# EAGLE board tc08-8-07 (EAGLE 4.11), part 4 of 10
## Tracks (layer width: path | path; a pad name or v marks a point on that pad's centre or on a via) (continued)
ENI  (via drill 0.61) (continued)
  Top 0.254: v55.92,263.19 54.33,261.61 54.33,259.7 54.65,259.38 54.65,258.75 54.33,258.43 54.33,249.23 55.28,248.27 A25.L1 | v57.82,265.1 66.39,273.67 66.39,280.02 77.51,291.13 v77.51,294.94 | v95.92,295.9 103.22,295.9 103.22,295.26 120.05,278.43 127.04,278.43 v127.04,276.85 | v136.56,275.9 v136.56,271.77 | v283.88,117.14 283.88,114.92 C07.L1 | v281.98,65.08 282.29,64.76 v282.29,50.15 | v273.4,50.15 273.4,40.31 v274.04,39.68 | v272.45,36.5 270.23,34.28 270.23,29.2 v270.55,28.88 | v260.7,26.66 259.43,26.66 v257.85,28.25 | v174.66,30.78 171.49,30.78 171.49,18.72 170.53,17.77 165.14,17.77 v165.14,19.35 | v160.69,18.72 158.47,20.94 155.29,20.94 v155.29,19.35 | v147.99,19.35 145.77,19.35 145.77,19.67 145.13,20.31 133.07,20.31 133.07,18.4 127.99,13.32 126.4,13.32 v126.4,13.96 | v17.82,58.72 15.59,60.95 15.59,74.28 12.1,77.77 12.1,87.94 12.42,88.25 12.42,199.38 v12.1,199.7
  Route2 0.254: v277.53,117.14 276.26,117.14 270.55,111.43 270.55,109.84 266.42,105.72 266.42,98.41 271.82,93.02 271.5,92.7 271.5,90.79 273.09,89.21 273.4,89.21 274.99,87.62 274.99,87.3 284.2,78.09 284.2,75.24 282.93,73.97 282.93,66.03 v281.98,65.08 | v165.14,19.35 163.23,21.26 v160.69,18.72 | v155.29,19.35 153.71,20.94 149.58,20.94 v147.99,19.35 | v12.1,199.7 20.04,207.63 20.99,207.63 25.12,211.76 25.12,212.71 36.23,223.83 36.23,224.14 40.36,228.27 40.36,230.49 53.69,243.83 53.69,245.42 55.28,247 A25.L1
  Route15 0.254: v167.68,272.4 167.99,272.4 174.34,266.05 174.34,265.1 v177.84,261.61 | v209.27,261.61 215.94,261.61 218.48,259.07 221.65,259.07 223.24,257.48 A12.H1 | v202.92,27.61 197.52,33.01 188.31,33.01 185.46,30.15 184.5,31.1 v184.19,31.1
  Bottom 0.254: v55.92,263.19 v57.82,265.1 | v77.51,294.94 77.82,294.63 81,294.63 82.27,295.9 v95.92,295.9 | v127.04,276.85 127.04,274.94 135.61,274.94 v136.56,275.9 | v136.56,271.77 136.88,271.45 144.18,271.45 144.5,271.77 165.77,271.77 166.41,272.4 v167.68,272.4 | v177.84,261.61 v209.27,261.61 | v283.88,117.14 282.29,118.73 279.12,118.73 v277.53,117.14 | v282.29,50.15 281.66,49.52 275.31,49.52 274.67,50.15 v273.4,50.15 | v274.04,39.68 272.77,38.4 272.77,36.5 v272.45,36.5 | v270.55,28.88 268.32,26.66 v260.7,26.66 | v257.85,28.25 256.89,27.29 238.16,27.29 237.53,26.66 234.03,26.66 233.4,27.29 208.95,27.29 208.63,27.61 205.78,27.61 205.46,27.29 203.24,27.29 v202.92,27.61 | v184.19,31.1 183.55,30.47 174.98,30.47 v174.66,30.78 | v126.4,13.96 125.77,14.59 109.89,14.59 108.94,15.54 61,15.54 v17.82,58.72
ENI\  (via drill 0.61)
  Top 0.254: v306.42,120.64 309.92,124.13 v309.92,124.77 | v324.52,139.37 324.2,139.69 324.2,145.08 326.43,147.31 326.43,152.71 v325.79,153.34 | v321.35,160.96 321.03,161.28 321.03,165.72 321.35,166.04 321.35,170.49 321.03,170.8 v321.03,173.66 | v328.33,175.56 328.33,177.15 B03.L2 | v287.37,107.3 C07.M1
  Route2 0.254: v296.26,110.16 296.26,110.48 v306.42,120.64 | v309.92,124.77 v322.3,137.15
  Route15 0.254: v325.79,153.34 320.71,158.42 320.71,160.33 v321.35,160.96
  Bottom 0.254: v287.37,107.3 288.01,106.67 291.5,106.67 293.41,108.57 294.68,108.57 v296.26,110.16 | v322.3,137.15 v324.52,139.37 | v321.03,173.66 323.25,175.88 328.01,175.88 v328.33,175.56
FR_00  (via drill 0.61)
  Top 0.254: 218.79,163.18 218.79,185.09 219.11,185.41 219.11,188.27 217.84,189.54 217.84,193.03 B12.E2 | 218.79,163.18 218.79,161.28 218.48,160.96 218.48,158.1 219.11,157.47 219.11,136.2 218.79,135.88 218.79,96.19 218.48,95.87 218.48,93.33 217.84,92.7 C12.U2 | v69.89,261.29 73.38,261.29 73.38,269.23 80.68,276.53 v82.59,276.53 | v89.89,278.12 97.51,285.74 97.51,292.41 98.78,293.68 101.64,293.68 101.64,268.91 v101.95,268.59 | v105.13,268.28 107.67,268.28 v107.67,264.47 | v130.21,263.19 130.53,262.88 v130.53,257.48 | v151.8,256.21 152.12,255.89 152.12,250.81 149.58,248.27 149.58,240.33 v151.48,238.43 | v262.29,152.39 261.97,152.07 v261.97,148.26 | 218.79,163.18 v219.43,163.18
  Route2 0.254: v82.59,276.53 83.54,277.48 86.71,277.48 88.3,279.07 88.94,279.07 v89.89,278.12 | v283.56,161.28 283.56,160.01 282.61,159.05 282.61,154.93 v280.39,152.71
  Route15 0.254: v156.88,237.8 156.88,237.48 159.42,234.94 160.37,234.94 170.22,225.09 171.17,225.09 180.06,216.21 181.01,216.21 v184.19,213.03 | v192.76,212.71 194.66,212.71 201.33,206.05 202.92,206.05 207.05,201.92 207.36,201.92 213.71,195.57 215.3,195.57 216.89,193.98 B12.E2 | v246.42,148.26 242.92,148.26 241.34,149.85 239.75,149.85 v227.37,162.23
  Bottom 0.254: v69.89,261.29 69.57,261.61 57.19,261.61 56.23,260.66 A25.F1 | v101.95,268.59 102.27,268.28 v105.13,268.28 | v107.67,264.47 107.99,264.78 125.45,264.78 127.99,262.24 129.26,262.24 v130.21,263.19 | v130.53,257.48 132.12,255.89 151.48,255.89 v151.8,256.21 | v151.48,238.43 153.07,236.84 155.29,236.84 156.25,237.8 v156.88,237.8 | v184.19,213.03 185.46,211.76 191.81,211.76 v192.76,212.71 | v283.56,161.28 284.83,162.55 286.42,162.55 286.74,162.23 B07.S1 | v280.39,152.71 278.8,151.12 269.91,151.12 269.59,151.43 266.1,151.43 265.78,151.12 263.56,151.12 v262.29,152.39 | v261.97,148.26 261.66,148.58 246.73,148.58 v246.42,148.26 | v227.37,162.23 226.41,163.18 v219.43,163.18
FR_00\  (via drill 0.61)
  Top 0.254: C12.P1 223.87,109.21 222.6,110.48 222.6,115.56 223.56,116.51 223.56,116.83 C12.K1 | v296.58,155.88 297.22,155.24 v297.22,153.98
  Route2 0.254: v246.42,142.55 246.1,142.23 245.46,142.23 242.92,139.69 242.61,139.69 225.14,122.22 225.14,121.59 224.19,120.64 224.19,118.1 C12.K1 | v265.78,143.18 268.64,140.32 272.77,144.45 273.4,144.45 v283.56,154.61
  Route15 0.254: v290.23,154.61 289.6,155.24 288.01,155.24 B07.U1
  Bottom 0.254: v290.23,154.61 290.55,154.29 294.36,154.29 295.95,155.88 v296.58,155.88 | v297.22,153.98 297.53,154.29 309.6,154.29 312.77,157.47 321.66,157.47 321.98,157.15 324.2,157.15 327.06,160.01 334.36,160.01 335,160.64 338.81,160.64 339.76,161.59 339.76,169.53 337.22,169.53 335.63,171.12 B03.N1 | v246.42,142.55 248,140.96 256.89,140.96 257.21,140.64 257.85,140.64 258.8,141.59 263.88,141.59 265.47,143.18 v265.78,143.18 | v283.56,154.61 284.2,155.24 286.74,155.24 B07.U1
FR_01  (via drill 0.61)
  Top 0.254: v222.6,16.5 222.6,29.51 221.02,31.1 D12.R1 | B07.V2 278.17,151.75 278.8,151.12 278.8,140.64 279.12,140.32 279.12,138.42 278.8,138.1 278.8,134.29 279.12,133.97 279.12,87.94 277.85,86.66 277.85,71.74 276.58,70.47 276.58,22.85 277.85,21.58 D07.V2 | v171.49,133.34 171.17,133.65 171.17,155.56 167.99,158.74 167.99,162.55 165.14,165.4 v165.14,173.66 | v171.17,173.66 171.17,188.58 171.8,189.22 171.8,196.84 v172.12,197.15 | v168.63,198.11 168.31,198.43 168.31,201.6 163.23,206.68 v163.23,218.11 | v157.83,218.11 155.93,220.02 155.93,255.89 v156.25,256.21 | v186.41,32.37 184.19,34.6 v184.19,38.4 | v29.88,68.25 25.75,72.38 25.75,229.22 26.07,229.54 26.07,230.81 25.75,231.13 v25.75,242.56 | v57.5,242.56 57.19,242.87 57.19,246.37 57.5,246.68 57.5,255.58 58.46,256.53 A25.H1
  Bottom 0.254: v222.6,16.5 266.74,16.5 267.37,17.13 272.45,17.13 274.36,19.04 D07.V2 | v171.49,133.34 171.8,133.34 176.25,128.89 181.01,128.89 183.23,131.11 183.23,131.75 182.92,132.07 182.92,132.7 C15.D1 | v165.14,173.66 165.45,173.34 171.17,173.34 | 171.17,173.34 184.19,173.34 185.14,174.3 B15.M1 | 156.25,258.43 244.19,258.43 245.15,257.48 248.64,257.48 A10.H1 | 156.25,258.43 77.19,258.43 76.87,258.11 74.01,258.11 73.7,258.43 60.36,258.43 59.41,257.48 A25.H1 | v171.17,173.66 171.17,173.34 | v172.12,197.15 171.17,198.11 v168.63,198.11 | v157.83,218.11 v163.23,218.11 | 156.25,258.43 v156.25,256.21 | v186.41,32.37 188.31,30.47 208.63,30.47 208.95,30.78 213.4,30.78 213.71,30.47 219.11,30.47 220.06,31.42 D12.R1 | v184.19,38.4 183.23,39.36 165.14,39.36 161.64,42.85 148.94,42.85 148.63,43.17 83.54,43.17 83.22,43.49 81.95,43.49 81.63,43.17 67.03,43.17 41.95,68.25 v29.88,68.25 | v25.75,242.56 v57.5,242.56
FR_01\  (via drill 0.61)
  Top 0.254: v305.79,150.48 305.47,150.8 305.47,154.61 305.15,154.93 305.15,171.12 v306.42,172.39 | v310.55,174.61 310.87,174.93 310.87,183.5 311.19,183.82 311.19,185.41 306.74,189.85 306.74,193.03 B05.E2 | v216.89,259.38 216.89,258.11 217.21,257.8 A12.H2 | v240.07,270.81 v241.97,272.72 | v247.69,272.72 248,273.04 248,285.1 260.07,297.17 275.94,297.17 v275.94,289.86 | v322.3,289.55 336.59,289.55 336.59,257.8 336.9,257.48 336.9,255.26 339.76,252.4 339.76,240.65 v338.81,239.7
  Route2 0.254: v240.07,270.81 v233.08,263.83 | v338.81,239.7 341.35,237.16 333.41,229.22 333.41,225.09 331.51,223.19 331.51,212.71 329.92,211.12 329.92,208.9 324.84,203.82 324.84,201.28 324.2,200.65 324.2,196.84 v322.62,195.25
  Bottom 0.254: v305.79,150.48 288.96,150.48 287.69,151.75 285.15,151.75 284.83,152.07 B07.V1 | v306.42,172.39 308.65,174.61 v310.55,174.61 | 322.62,194.93 308.96,194.93 308.01,193.98 307.06,193.98 B05.E2 | 322.62,194.93 326.43,194.93 328.01,196.52 B03.D2 | v216.89,259.38 216.89,262.24 231.49,262.24 v233.08,263.83 | v241.97,272.72 242.29,272.4 244.83,272.4 245.46,271.77 246.73,271.77 v247.69,272.72 | v275.94,289.86 276.26,289.55 v322.3,289.55 | v322.62,195.25 322.62,194.93
FR_02  (via drill 0.61)
  Top 0.254: v268.64,18.09 268.64,15.86 268.01,15.23 266.42,15.23 266.42,20.31 v265.47,21.26 | v262.29,18.72 262.29,15.23 256.58,9.51 231.49,9.51 v231.49,18.09 | v211.49,17.77 201.33,7.61 31.47,7.61 31.47,99.68 31.15,100 31.15,100.63 31.47,100.95 31.47,147.94 28.93,150.48 28.93,220.02 v29.25,220.33 | v19.09,220.97 18.77,221.29 v18.77,255.26 | v272.45,92.38 272.45,89.84 273.09,89.21 v273.09,88.25 | v293.09,58.72 292.77,58.41 292.77,54.92 292.45,54.6 292.45,53.33 294.99,50.79 294.99,48.25 295.31,47.93 v295.31,46.34 | v282.93,39.36 282.61,39.04 282.61,26.66 281.98,26.02 281.98,23.48 281.34,22.85 D07.U2
  Route2 0.254: v265.47,21.26 264.83,21.26 v262.29,18.72 | v217.52,17.13 213.4,17.13 212.13,18.4 v211.49,17.77 | v272.45,92.38 277.85,97.78 278.48,97.78 286.42,105.72 286.42,107.62 289.6,110.8 285.47,114.92 285.47,126.67 287.06,128.26 287.06,129.53 C07.E1
  Route15 0.254: v273.09,88.25 273.09,87.94 275.94,85.08 275.94,82.86 284.83,73.97 284.83,71.11 285.47,70.47 285.47,66.35 v293.09,58.72
  Bottom 0.254: v268.64,18.09 268.96,17.77 272.13,17.77 274.67,20.31 278.8,20.31 280.39,21.89 D07.U2 | v231.49,18.09 231.18,17.77 223.56,17.77 223.24,18.09 221.65,18.09 220.7,17.13 v217.52,17.13 | v29.25,220.33 28.61,220.97 v19.09,220.97 | v18.77,255.26 19.4,255.89 30.2,255.89 32.74,258.43 53.06,258.43 55.28,256.21 55.28,254.62 A25.J1 | v295.31,46.34 295.31,44.44 293.41,44.44 288.33,39.36 v282.93,39.36
FR_02\  (via drill 0.61)
  Top 0.254: v326.43,164.77 326.74,165.09 326.74,172.71 v326.43,173.02 | v329.28,185.73 v329.28,188.27 | v331.19,190.17 331.51,190.49 331.51,193.03 B03.E2 | v284.2,129.53 C07.F1
  Route2 0.254: v299.76,133.65 299.76,134.29 318.49,153.02 318.81,153.02 320.08,154.29 320.08,154.61 323.89,158.42 323.89,162.23 v326.43,164.77 | v326.43,173.02 326.43,173.66 326.74,173.98 326.74,176.83 327.06,177.15 327.06,178.42 v332.46,183.82 | v329.28,188.27 v331.19,190.17
  Bottom 0.254: v284.2,129.53 286.74,132.07 291.5,132.07 293.09,133.65 295.31,133.65 296.26,134.61 298.49,134.61 299.44,133.65 v299.76,133.65 | v332.46,183.82 330.55,185.73 v329.28,185.73
FR_03  (via drill 0.61)
  Top 0.254: v28.29,245.73 28.29,230.49 v26.71,228.9 | v16.55,201.6 16.23,201.28 16.23,156.2 v17.82,154.61 | v83.86,182.55 82.9,181.6 82.9,176.83 79.73,173.66 79.73,151.75 80.36,151.12 v80.36,148.58 79.73,147.94 79.73,55.87 v81.32,54.28 | v176.57,169.21 175.61,168.26 175.61,165.4 B15.R2 | v294.04,26.98 295.31,28.25 295.31,32.06 295.63,32.37 295.63,37.45 295.31,37.77 295.31,41.58 293.72,43.17 v293.72,45.71 | v180.69,15.54 181.01,15.86 181.01,30.47 178.15,33.32 178.15,33.96 v177.52,34.6 | v156.56,35.23 158.47,37.14 158.47,39.68 v154.34,43.8 | v144.82,41.58 143.23,43.17 143.23,46.03 v143.86,46.66 | v281.34,62.85 279.75,61.27 v279.75,56.5
  Route2 0.254: v284.52,124.13 284.52,122.86 282.93,121.27 282.93,117.46 v281.34,115.88 | v296.26,91.11 296.26,90.16 295.63,89.52 295.63,87.3 287.37,79.05 287.37,74.92 286.1,73.65 286.1,68.88 284.52,67.3 284.52,66.03 v281.34,62.85
  Route15 0.254: v26.71,228.9 v23.53,225.73 | v118.78,186.36 122.27,182.87 v122.27,182.55 | v128.31,183.18 128.62,183.18 129.26,182.55 130.21,182.55 v134.66,178.11 | v160.06,176.83 161.64,175.25 161.64,174.61 162.91,173.34 163.55,173.34 v169.26,167.63 | v274.36,31.42 262.61,19.67 260.07,19.67 259.43,20.31 253.08,20.31 249.91,23.48 248.32,23.48 v247.69,22.85 | v151.17,40.63 v154.34,43.8 | v281.34,115.88 284.52,115.88 288.64,111.75 288.64,108.25 288.96,107.94 288.96,106.67 291.18,104.44 291.18,102.86 294.99,99.05 294.99,98.1 295.63,97.46 296.58,97.46 298.49,95.55 298.49,93.02 298.8,92.7 298.8,92.06 297.22,90.47 296.58,91.11 v296.26,91.11 | v293.72,45.71 v284.52,54.92
  Bottom 0.254: v28.29,245.73 49.57,245.73 52.74,248.91 56.55,248.91 58.14,250.49 A25.K1 | v23.53,225.73 21.94,224.14 19.72,224.14 17.82,226.05 17.18,226.05 9.88,218.74 9.88,201.6 v16.55,201.6 | v17.82,154.61 21.63,150.8 21.63,149.21 78.46,149.21 79.09,148.58 v80.36,148.58 | v83.86,182.55 84.17,182.87 109.57,182.87 112.75,186.04 118.46,186.04 v118.78,186.36 | v122.27,182.55 122.59,182.87 126.72,182.87 127.04,183.18 v128.31,183.18 | v134.66,178.11 135.61,177.15 136.88,177.15 137.51,176.52 159.74,176.52 v160.06,176.83 | v169.26,167.63 169.9,166.99 176.88,166.99 177.52,167.63 177.52,169.21 v176.57,169.21 | v294.04,26.98 290.23,26.98 284.52,21.26 284.52,19.67 D07.V1 | v293.72,45.71 290.55,42.53 286.42,42.53 284.52,40.63 282.29,40.63 281.66,39.99 279.75,39.99 279.12,39.36 279.12,33.01 275.94,33.01 v274.36,31.42 | v247.69,22.85 247.05,23.48 241.34,23.48 240.38,22.53 238.8,22.53 236.57,20.31 218.79,20.31 213.71,15.23 181.01,15.23 v180.69,15.54 | v177.52,34.6 176.57,33.64 169.9,33.64 169.26,34.28 167.99,34.28 167.36,33.64 159.1,33.64 157.52,35.23 v156.56,35.23 | v151.17,40.63 150.53,39.99 146.4,39.99 v144.82,41.58 | v143.86,46.66 143.86,47.93 142.28,49.52 86.08,49.52 v81.32,54.28 | v284.52,124.13 281.66,124.13 C07.H2 | v279.75,56.5 281.02,55.23 284.2,55.23 v284.52,54.92
FR_03\  (via drill 0.61)
  Top 0.254: v312.14,122.22 311.5,122.86 311.5,139.37 v313.41,141.27 | v319.44,144.77 318.49,145.72 v318.49,153.98 | v341.35,166.68 341.67,166.99 v341.67,169.85 | v341.03,179.37 v341.03,182.23 | v277.85,123.49 C07.J2 | v313.73,164.45 314.04,164.14 314.04,158.74 v313.73,158.42
  Route2 0.254: v316.58,144.45 v313.41,141.27
  Route15 0.254: v291.18,122.86 293.09,120.96 294.99,120.96 v296.26,122.22 | v293.41,183.18 294.99,181.6 294.99,177.79 295.31,177.47 295.31,176.2 v302.3,169.21 | v315.63,156.52 v313.73,158.42
  Bottom 0.254: v277.85,123.49 278.17,123.18 279.75,123.18 280.39,122.54 290.87,122.54 v291.18,122.86 | v296.26,122.22 296.58,122.54 311.82,122.54 v312.14,122.22 | v316.58,144.45 316.9,144.77 v319.44,144.77 | v341.35,166.68 342.62,166.68 342.62,163.5 336.27,157.15 325.16,157.15 322.3,154.29 318.81,154.29 v318.49,153.98 318.17,154.29 317.85,154.29 v315.63,156.52 | v341.67,169.85 342.62,170.8 342.62,179.37 v341.03,179.37 | v341.03,182.23 333.41,182.23 332.46,181.28 B03.K2 | v293.41,183.18 293.09,182.87 269.28,182.87 268.01,184.14 B08.J2 | v302.3,169.21 302.3,166.99 309.92,166.99 312.46,164.45 v313.73,164.45
GND  (via drill 0.61)
  Top 0.635: D11.P1 236.89,34.28 236.89,30.47 238.16,29.2 238.16,27.93 235.94,25.71 234.03,25.71 D11.T1 | D04.U2 319.76,22.53 321.98,24.75 D04.T1 321.98,26.02 321.98,31.1 D04.R1 321.98,32.37 321.98,37.45 D04.N1 | D03.R2 328.33,32.37 328.33,37.45 D03.N2 328.33,38.72 328.33,43.8 D03.L2 328.33,45.07 328.33,50.15 D03.J2 D03.F2 | D02.U2 345.16,22.53 347.06,22.53 347.06,25.07 D02.T1 347.38,26.02 347.38,31.1 D02.R1 347.38,32.37 347.38,37.45 D02.N1 | D03.U2 332.46,22.53 334.68,24.75 D03.T1 D03.R1 334.68,32.37 334.68,37.45 D03.N1 | D02.N2 341.03,37.45 341.03,32.37 D02.R2 | D05.U2 307.06,22.53 309.28,24.75 D05.T1 309.28,26.02 309.28,31.1 D05.R1 309.28,32.37 309.28,37.45 D05.N1 D05.L1 | D05.S1 312.46,29.2 312.46,34.28 D05.P1 312.46,35.55 312.46,40.63 D05.M1 312.46,41.9 312.46,46.98 D05.K1 | D04.R2 D04.N2 D04.L2 D04.J2 | D02.L2 341.03,45.07 341.03,50.15 D02.J2 341.03,51.42 341.03,56.5 D02.F2 | D05.F1 309.28,56.5 309.28,51.42 D05.J1 | D05.E1 312.46,59.68 312.46,54.6 D05.H1 | D06.F2 290.23,56.5 290.23,51.42 D06.J2 290.23,50.15 290.23,45.07 D06.L2 290.23,43.8 290.23,38.72 D06.N2 290.23,37.45 290.23,32.37 D06.R2 | D07.T1 284.52,24.75 286.74,22.53 D07.U1 | D06.U2 294.36,22.53 296.58,24.75 D06.T1 296.58,26.02 296.58,31.1 D06.R1 296.58,32.37 296.58,37.45 D06.N1 | D05.R2 302.93,32.37 302.93,37.45 D05.N2 D05.L2 | D03.A1 337.86,72.38 337.86,67.3 D03.C1 | D02.A1 350.56,72.38 350.56,67.3 D02.C1 | D04.C1 D04.A1 | D06.A1 299.76,72.38 299.76,67.3 D06.C1 | D05.J2 302.93,51.42 302.93,56.5 D05.F2 302.93,57.77 302.93,62.85 D05.D2 | D05.C1 D05.A1 312.77,88.57 310.23,91.11 310.23,94.28 309.92,94.6 C05.T1
  Top 0.635: B02.T1 347.38,158.1 347.38,153.02 B02.V1 | B03.T1 334.68,158.1 334.68,153.02 B03.V1 | B04.T1 321.98,158.1 321.98,153.02 B04.V1 | C05.C2 306.74,137.15 307.38,137.78 307.38,140.64 309.6,142.86 B05.V1 309.28,153.02 309.28,158.1 B05.T1 309.92,159.37 309.92,162.23 311.19,163.5 311.19,166.36 312.46,167.63 B05.P1 312.46,168.9 312.46,171.44 310.55,173.34 307.38,173.34 307.38,175.56 307.22,175.72 | 79.89,252.56 79.41,252.08 79.41,246.37 78.14,245.1 A23.M2 | 79.89,252.56 80.68,253.35 A23.J1 | 79.89,252.56 79.73,252.72 76.24,256.21 76.24,258.43 74.97,259.7 A23.F2 74.97,260.97 75.6,261.61 75.6,265.42 77.51,267.32 77.51,269.23 A23.C2 | AB19.AS2 AB19.AU2 128.31,226.05 126.08,228.27 AB19.AT2 125.13,229.22 125.13,234.3 AB19.AR2 125.77,235.57 126.4,236.21 126.4,240.02 127.04,240.65 127.04,248.91 128.31,250.18 AB19.AK2 127.99,251.13 126.88,252.24 | 126.88,252.24 125.77,253.35 AB19.AJ2 | AB19.AC2 128.31,269.23 127.04,267.96 127.04,252.4 126.88,252.24 | A02.T1 A02.R1 347.38,235.57 347.38,240.65 A02.N1 | A04.U2 319.76,225.73 321.98,227.95 A04.T1 321.98,229.22 321.98,234.3 A04.R1 321.98,235.57 321.98,240.65 A04.N1 | A03.N2 328.33,240.65 328.33,235.57 A03.R2 | A03.T1 334.68,229.22 334.68,234.3 A03.R1 A03.N1 | A02.R2 A02.N2 341.03,241.92 341.03,247 A02.L2 341.03,248.27 341.03,253.35 A02.J2 341.03,254.62 341.03,259.7 A02.F2 | AB01.AL2 354.68,247.96 356.91,250.18 AB01.AK2 356.91,251.45 356.91,256.53 AB01.AH2 | A05.U2 307.06,225.73 309.28,227.95 A05.T1 309.28,229.22 309.28,234.3 A05.R1 | A05.S1 A05.P1 | A05.L1 309.28,247 309.28,241.92 A05.N1 | A05.K1 A05.M1 | A05.J1 309.28,254.62 309.28,259.7 A05.F1 309.28,260.97 309.28,266.05 A05.D1 308.96,267 306.74,269.23 A05.C2 307.06,270.18 309.28,272.4 A05.B1 310.23,273.36 312.46,275.58 A05.A1
  Top 0.635: A03.L2 328.33,248.27 328.33,253.35 A03.J2 328.33,254.62 328.33,259.7 A03.F2 | A04.F2 315.63,259.7 315.63,254.62 A04.J2 315.63,253.35 315.63,248.27 A04.L2 315.63,247 315.63,241.92 A04.N2 315.63,240.65 315.63,235.57 A04.R2 | A06.J2 A06.F2 | A06.R2 290.23,235.57 290.23,240.65 A06.N2 290.23,241.92 290.23,247 A06.L2 | A06.N1 296.58,240.65 296.58,235.57 A06.R1 A06.T1 | A05.R2 302.93,235.57 302.93,240.65 A05.N2 302.93,241.92 302.93,247 A05.L2 A05.J2 302.93,254.62 302.93,259.7 A05.F2 A05.D2 | A06.A1 299.76,275.58 299.76,270.5 A06.C1 | A04.A1 325.16,275.58 325.16,270.5 A04.C1 | A03.A1 337.86,275.58 337.86,270.5 A03.C1 | A02.A1 350.56,275.58 350.56,270.5 A02.C1 | AB19.BM2 128.31,175.25 128.31,176.2 126.72,176.2 125.77,177.15 AB19.BL2 125.13,178.42 124.5,179.06 124.5,182.87 123.86,183.5 123.86,185.73 125.13,186.99 125.13,189.85 AB19.BF2 126.08,190.8 128.31,193.03 AB19.BE2 | B22.V1 93.38,153.02 93.38,158.1 B22.T1 93.38,159.37 92.75,160.01 92.75,163.82 92.11,164.45 92.11,198.11 90.84,199.38 B22.C2 | B23.C2 78.14,200.65 78.14,203.51 80.68,206.05 80.68,221.6 A23.V1 80.68,222.87 80.68,227.95 A23.T1 81.32,229.22 81.32,231.13 84.17,233.99 A23.P1 v84.17,242.56 | A14.T1 194.98,227.95 194.35,227.32 194.35,223.51 193.71,222.87 193.71,219.06 194.03,218.74 194.03,205.09 192.44,203.51 192.44,200.65 B14.C2 | AB01.BL2 354.68,178.11 356.91,180.33 AB01.BK2 356.91,181.6 356.91,186.68 AB01.BH2 356.91,187.95 356.27,188.58 356.27,192.39 355.64,193.03 355.64,197.79 355.48,197.95 | 355.48,197.95 356.91,199.38 AB01.BC2 | 355.48,197.95 354.68,197.15 AB01.BD2 | 307.22,175.72 308.01,176.52 308.01,178.74 309.6,180.33 B05.J1 308.96,184.46 306.74,184.46 306.74,184.77 303.57,187.95 303.57,189.85 B05.F2 303.57,191.12 304.2,191.76 304.2,195.57 306.11,197.47 306.11,199.38 B05.C2
  Top 0.635: 307.22,175.72 306.74,175.25 B05.M2 | A07.T1 283.88,227.95 283.25,227.32 283.25,223.51 282.61,222.87 282.61,217.79 283.88,216.52 283.88,206.36 281.34,203.82 281.34,200.65 B07.C2 | C01.T1 360.08,95.87 359.45,96.51 359.45,100.32 358.81,100.95 358.81,114.92 359.13,115.24 359.13,119.69 358.81,120 358.81,131.75 357.54,133.02 357.54,135.88 C01.C2
  Bottom 0.635: CD18.AT1 145.13,94.92 145.45,94.6 149.26,94.6 150.21,93.65 151.48,93.65 152.75,94.92 156.56,94.92 C17.T1 157.83,94.92 158.47,94.28 162.28,94.28 162.91,93.65 164.18,93.65 165.45,94.92 169.26,94.92 C16.T1 170.53,95.55 171.8,96.83 177.84,96.83 179.11,95.55 181.96,95.55 C15.T1 183.23,94.92 186.09,94.92 187.36,93.65 189.58,93.65 190.22,94.28 194.03,94.28 194.66,94.92 C14.T1 195.93,94.92 196.57,94.92 197.84,93.65 202.28,93.65 202.92,94.28 206.73,94.28 207.36,94.92 C13.T1 208.63,95.55 208.95,95.87 212.76,95.87 213.71,96.83 215.62,96.83 217.21,95.24 C12.T1 221.33,95.55 225.14,95.55 226.41,96.83 228.32,96.83 229.59,95.55 232.76,95.55 C11.T1 234.03,94.92 234.67,94.28 238.48,94.28 239.11,93.65 241.65,93.65 243.24,95.24 C10.T1 246.73,94.92 247.37,94.28 251.18,94.28 251.81,93.65 253.4,93.65 254.99,95.24 C09.T1 259.43,94.92 260.07,94.28 263.88,94.28 264.51,93.65 265.78,93.65 267.37,95.24 C08.T1 272.13,94.92 275.94,94.92 277.21,93.65 279.44,93.65 280.71,94.92 283.56,94.92 C07.T1 284.83,95.55 285.47,96.19 289.28,96.19 289.91,96.83 294.36,96.83 295.63,95.55 296.26,95.55 C06.T1 297.53,94.92 298.17,94.28 301.98,94.28 302.61,93.65 306.74,93.65 308.01,94.92 308.96,94.92 C05.T1 313.73,95.24 315.31,93.65 316.58,93.65 317.54,94.6 321.35,94.6 321.66,94.92 C04.T1 322.93,94.92 323.25,94.6 327.06,94.6 328.01,93.65 329.28,93.65 330.55,94.92 334.36,94.92 C03.T1 338.81,95.24 340.4,93.65 341.98,93.65 343.25,94.92 347.06,94.92 C02.T1 348.33,94.92 352.14,94.92 353.41,93.65 355.64,93.65 356.91,94.92 359.76,94.92 C01.T1
  Bottom 0.635: CD18.BT1 145.13,25.07 145.45,24.75 149.26,24.75 150.21,23.8 151.48,23.8 152.75,25.07 156.56,25.07 D17.T1 157.83,25.07 158.47,24.44 162.28,24.44 162.91,23.8 164.5,23.8 166.09,25.39 D16.T1 170.53,25.07 171.17,24.44 174.98,24.44 175.61,23.8 177.84,23.8 178.79,24.75 182.28,24.75 D15.T1 183.23,25.07 187.04,25.07 188.31,23.8 189.58,23.8 190.22,24.44 194.03,24.44 194.66,25.07 D14.T1 195.93,25.07 196.57,24.44 200.38,24.44 201.01,23.8 203.24,23.8 204.82,25.39 D13.T1 208.63,25.07 208.95,24.75 212.76,24.75 213.71,23.8 215.94,23.8 217.21,25.07 220.06,25.07 D12.T1 D11.T2 227.68,25.07 232.76,25.07 D11.T1 234.03,25.07 235.3,23.8 240.38,23.8 241.02,24.44 244.83,24.44 245.46,25.07 D10.T1 246.73,25.07 247.37,25.07 248.64,23.8 253.08,23.8 254.35,25.07 258.16,25.07 D09.T1 259.43,25.07 262.29,25.07 263.56,23.8 265.78,23.8 266.74,24.75 270.55,24.75 270.86,25.07 D08.T1 272.13,25.07 272.45,24.75 276.26,24.75 277.21,23.8 279.12,23.8 280.39,25.07 283.56,25.07 D07.T1 | CD18.BC2 141.96,66.35 142.28,66.03 146.09,66.03 147.04,65.08 148.31,65.08 149.58,66.35 153.39,66.35 D17.C2 154.66,66.35 157.52,66.35 158.79,65.08 161.01,65.08 161.64,65.71 165.45,65.71 166.09,66.35 D16.C2 167.36,66.35 170.22,66.35 171.49,65.08 173.71,65.08 174.34,65.71 178.15,65.71 178.79,66.35 D15.C2 180.06,66.35 180.69,65.71 184.5,65.71 185.14,65.08 186.41,65.08 187.68,66.35 191.49,66.35 D14.C2 192.76,66.35 193.08,66.03 196.89,66.03 197.84,65.08 202.92,65.08 204.19,66.35 D13.C2 205.46,66.35 206.41,65.39 210.22,65.39 210.54,65.08 211.81,65.08 213.08,66.35 216.89,66.35 D12.C2 218.16,66.98 218.79,67.61 222.6,67.61 223.24,68.25 225.78,68.25 227.05,66.98 229.59,66.98 D11.C2 230.86,66.35 231.18,66.03 234.99,66.03 235.94,65.08 238.48,65.08 240.07,66.66 D10.C2 243.56,66.35 244.19,65.71 248,65.71 248.64,65.08 249.91,65.08 251.18,66.35 254.99,66.35 D09.C2 256.26,66.35 257.53,65.08 262.61,65.08 263.88,66.35 267.69,66.35 D08.C2 268.96,66.35 270.23,65.08 275.63,65.08 277.21,66.66 D07.C2 281.66,66.35 285.47,66.35 286.74,65.08 288.01,65.08 289.6,66.66 D06.C2 294.36,66.35 299.44,66.35 D06.C1 D05.C2
  Bottom 0.635: D03.R2 328.01,31.42 322.93,31.42 D04.R1 | D02.R2 340.71,31.42 335.63,31.42 D03.R1 | D02.N1 347.06,37.77 341.98,37.77 D02.N2 | D03.N2 329.28,37.77 334.36,37.77 D03.N1 | D05.R1 309.92,31.1 312.14,28.88 D05.S1 313.41,28.88 315.63,31.1 D04.R2 | D03.K1 338.49,46.98 340.71,44.75 D02.L2 341.98,44.75 343.89,44.75 346.43,47.29 350.24,47.29 D02.K1 | D02.F1 347.06,56.82 341.98,56.82 D02.F2 340.71,56.82 335.63,56.82 D03.F1 334.36,56.82 329.28,56.82 D03.F2 D04.F1 321.66,56.82 316.58,56.82 D04.F2 315.63,56.5 313.41,54.28 D05.H1 | D05.J1 310.23,51.1 312.46,53.33 D05.H1 | D04.J2 315.31,51.1 313.09,53.33 D05.H1 | D04.K1 325.79,46.98 328.01,44.75 D03.L2 | D06.L2 290.87,45.07 293.09,47.29 D06.K2 D06.K1 300.71,47.93 302.93,50.15 D05.J2 | D06.F1 296.26,56.82 291.18,56.82 D06.F2 | D07.U1 288.01,21.89 293.09,21.89 D06.U2 | D06.R2 291.18,31.42 296.26,31.42 D06.R1 297.53,31.42 302.61,31.42 D05.R2 | D02.C1 350.24,66.35 345.16,66.35 D02.C2 343.89,66.35 338.81,66.35 D03.C1 D03.C2 331.19,66.35 326.11,66.35 D04.C1 D04.C2 318.49,66.35 313.41,66.35 D05.C1 312.46,66.03 310.23,63.81 D05.D1 308.96,63.81 306.74,66.03 D05.C2 | D05.D2 303.88,63.81 306.11,66.03 D05.C2 | D05.B1 309.28,69.2 307.06,66.98 D05.C2 | D05.N1 308.96,37.77 303.88,37.77 D05.N2 | CD18.AC2 141.96,136.2 142.59,135.56 146.4,135.56 147.04,134.93 149.26,134.93 150.53,136.2 153.39,136.2 C17.C2 154.66,136.2 155.29,135.56 159.1,135.56 159.74,134.93 161.96,134.93 163.23,136.2 166.09,136.2 C16.C2 167.36,136.2 167.99,135.56 171.8,135.56 172.44,134.93 174.66,134.93 175.93,136.2 178.79,136.2 C15.C2 180.06,136.2 180.69,135.56 184.5,135.56 185.14,134.93 186.41,134.93 187.68,136.2 191.49,136.2 C14.C2 192.76,136.2 193.39,135.56 197.2,135.56 197.84,134.93 201.97,134.93 203.24,136.2 204.19,136.2 C13.C2 205.46,136.2 206.09,135.56 209.9,135.56 210.54,134.93 212.76,134.93 214.03,136.2 216.89,136.2 C12.C2 218.16,136.2 218.79,135.56 222.6,135.56 223.24,134.93 225.46,134.93 226.73,136.2 229.59,136.2 C11.C2 230.86,136.2 234.67,136.2 235.94,134.93 237.21,134.93 238.48,136.2 242.29,136.2 C10.C2 243.56,136.2 246.42,136.2 247.69,134.93 249.91,134.93 250.54,135.56 254.35,135.56 254.99,136.2 C09.C2 256.26,136.2 259.12,136.2 260.39,134.93 262.61,134.93 263.88,136.2 267.69,136.2 C08.C2 268.96,136.2 269.59,135.56 273.4,135.56 274.04,134.93 277.53,134.93 279.12,136.51 C07.C2 281.66,136.2 282.93,134.93 291.82,134.93 293.09,136.2 C06.C2 294.36,136.2 294.99,135.56 298.8,135.56 299.44,134.93 300.71,134.93 301.98,136.2 305.79,136.2 C05.C2 306.74,135.88 311.19,135.88 312.14,134.93 313.41,134.93 314.68,136.2 318.49,136.2 C04.C2 319.76,136.2 320.08,135.88 323.89,135.88 324.84,134.93 326.11,134.93 327.38,136.2 331.19,136.2 C03.C2 332.46,136.2 335.32,136.2 336.59,134.93 338.81,134.93 339.76,135.88 343.57,135.88 343.89,136.2 C02.C2 345.16,136.2 348.02,136.2 349.29,134.93 351.51,134.93 352.14,135.56 355.95,135.56 356.59,136.2 C01.C2
  Bottom 0.635: B16.T1 170.53,158.42 170.85,158.1 174.66,158.1 175.61,157.15 176.88,157.15 178.15,158.42 181.96,158.42 B15.T1 183.23,158.42 186.09,158.42 187.36,157.15 189.58,157.15 190.22,157.79 194.03,157.79 194.66,158.42 B14.T1 195.93,158.42 198.79,158.42 200.06,157.15 202.28,157.15 203.24,158.1 207.05,158.1 207.36,158.42 B13.T1 208.63,158.42 211.49,158.42 212.76,157.15 214.98,157.15 215.62,157.79 219.43,157.79 220.06,158.42 B12.T1 221.33,158.42 221.65,158.1 225.46,158.1 226.41,157.15 229.27,157.15 230.54,158.42 232.76,158.42 B11.T1 234.03,158.42 234.67,158.42 235.94,157.15 240.38,157.15 241.02,157.79 244.83,157.79 245.46,158.42 B10.T1 246.73,158.42 247.37,157.79 251.18,157.79 251.81,157.15 254.04,157.15 255.62,158.74 B09.T1 259.43,158.42 260.07,157.79 263.88,157.79 264.51,157.15 266.1,157.15 267.69,158.74 B08.T1 272.13,158.42 274.99,158.42 276.26,157.15 282.29,157.15 283.56,158.42 B07.T1 284.83,158.42 288.64,158.42 289.91,157.15 291.18,157.15 292.45,158.42 296.26,158.42 B06.T1 297.53,158.42 297.85,158.1 301.66,158.1 302.61,157.15 304.84,157.15 306.11,158.42 308.96,158.42 B05.T1 | AB01.BT1 359.76,158.42 356.91,158.42 354.37,155.88 351.51,155.88 B02.U1 350.56,154.93 348.33,152.71 B02.V1 347.06,152.71 343.25,152.71 341.67,154.29 340.4,154.29 339.44,155.24 338.81,155.24 B03.U1 337.86,154.93 335.63,152.71 B03.V1 334.36,152.71 330.55,152.71 328.01,155.24 326.11,155.24 B04.U1 325.16,154.93 322.93,152.71 B04.V1 321.66,152.71 317.85,152.71 315.31,155.24 313.41,155.24 B05.U1 312.46,154.93 310.23,152.71 B05.V1
  Bottom 0.635: A25.M1 59.41,244.14 60.68,242.87 73.06,242.87 74.33,244.14 77.19,244.14 A23.M2 78.46,244.14 82.27,244.14 83.54,242.87 84.17,242.87 | 84.17,242.87 84.81,242.87 85.76,243.83 89.57,243.83 89.89,244.14 A22.M2 | A26.D2 37.18,267 37.82,267.64 41.63,267.64 42.26,268.28 72.11,268.28 73.38,269.55 77.19,269.55 A23.C2 A23.C1 84.81,269.55 89.89,269.55 A22.C2 91.16,269.55 91.79,268.91 95.6,268.91 96.24,268.28 98.46,268.28 100.05,269.86 A21.C2 103.86,269.55 107.67,269.55 108.94,268.28 114.02,268.28 115.29,269.55 A20.C2 116.56,269.55 117.51,268.59 121.32,268.59 121.64,268.28 123.86,268.28 125.13,269.55 127.99,269.55 AB19.AC2 129.26,269.55 132.75,269.55 134.02,268.28 135.61,268.28 136.24,268.91 140.05,268.91 140.69,269.55 A18.C2 141.96,269.55 144.82,269.55 146.09,268.28 161.01,268.28 161.64,268.91 165.45,268.91 166.09,269.55 A16.C2 167.36,269.55 167.99,268.91 171.8,268.91 172.44,268.28 174.66,268.28 175.93,269.55 178.79,269.55 A15.C2 180.06,269.55 183.87,269.55 185.14,268.28 186.41,268.28 187.04,268.91 190.85,268.91 191.49,269.55 A14.C2 | A02.U2 345.16,225.73 347.38,227.95 A02.T1 348.33,228.27 352.14,228.27 353.41,227 354.68,227 355.64,227.95 359.45,227.95 359.76,228.27 AB01.AT1 | A04.R1 322.93,234.62 328.01,234.62 A03.R2 329.28,234.62 334.36,234.62 A03.R1 A02.R2 | A03.U2 332.14,226.05 334.36,228.27 A03.T1 | A02.N1 347.06,240.97 341.98,240.97 A02.N2 | A02.K1 351.51,250.49 356.59,250.49 AB01.AK2 | A03.K1 338.49,250.18 340.71,247.96 A02.L2 | AB01.AH2 356.59,257.48 355.32,258.75 349.6,258.75 348.33,260.02 A02.F1 347.06,260.02 341.98,260.02 A02.F2 340.71,260.02 335.63,260.02 A03.F1 334.36,260.02 329.28,260.02 A03.F2 328.01,260.02 322.93,260.02 A04.F1 321.66,260.02 316.58,260.02 A04.F2 315.31,260.66 313.09,262.88 A05.E1
  Bottom 0.635: A05.S1 312.46,232.4 309.6,232.4 A05.R1 A04.R2 | A05.N1 309.92,240.65 312.14,238.43 A05.P1 | A05.M1 313.09,243.83 315.31,241.61 A04.N2 | A05.J1 309.92,253.35 309.92,251.13 312.14,251.13 A05.K1 | A05.H1 312.46,257.8 312.46,259.7 309.92,259.7 A05.F1 | A04.K1 325.79,250.18 328.01,247.96 A03.L2 | A12.T1 221.33,228.27 221.97,227.64 225.78,227.64 226.41,227 230.54,227 231.81,228.27 232.76,228.27 A11.T1 234.03,228.27 235.3,227 240.38,227 241.34,227.95 245.15,227.95 245.46,228.27 A10.T1 246.73,228.27 247.05,227.95 250.86,227.95 251.81,227 254.04,227 255.31,228.27 258.16,228.27 A09.T1 259.43,228.27 264.51,228.27 A08.T2 A08.T1 272.13,228.27 272.45,227.95 276.26,227.95 277.21,227 285.15,227 285.31,227.16 | 285.31,227.16 286.74,225.73 A07.U1 288.01,225.09 293.09,225.09 A06.U2 294.36,225.73 296.58,227.95 A06.T1 | 285.31,227.16 284.52,227.95 A07.T1 | A12.C2 218.16,269.55 218.79,268.91 222.6,268.91 223.24,268.28 225.46,268.28 226.73,269.55 229.59,269.55 A11.C2 230.86,269.55 232.13,268.28 237.21,268.28 238.48,269.55 242.29,269.55 A10.C2 243.56,269.55 246.42,269.55 247.69,268.28 249.91,268.28 251.18,269.55 254.99,269.55 A09.C2 256.26,269.55 256.89,268.91 260.7,268.91 261.34,268.28 263.56,268.28 264.83,269.55 267.69,269.55 A08.C2 268.96,269.55 269.59,268.91 273.4,268.91 274.04,268.28 276.26,268.28 276.9,268.91 279.75,268.91 280.39,269.55 A07.C2 281.66,269.55 282.93,268.28 291.18,268.28 291.5,268.59 292.14,268.59 293.09,269.55 A06.C2 294.36,269.55 299.44,269.55 A06.C1 300.71,269.55 305.79,269.55 A05.C2 | A06.L2 291.18,247.96 293.41,250.18 A06.K2
  Bottom 0.635: A06.J2 290.87,253.35 293.09,251.13 A06.K2 | A06.K2 A06.K1 | A06.F1 296.26,260.02 291.18,260.02 A06.F2 | A06.R2 291.18,234.62 296.26,234.62 A06.R1 A05.R2 | A05.B1 309.92,272.4 312.14,270.18 A05.C1 313.41,269.55 318.49,269.55 A04.C2 319.76,269.55 324.84,269.55 A04.C1 326.11,269.55 331.19,269.55 A03.C2 332.46,269.55 337.54,269.55 A03.C1 338.81,269.55 343.89,269.55 A02.C2 345.16,269.55 350.24,269.55 A02.C1 351.51,269.55 356.59,269.55 AB01.AC2 | A05.D2 303.88,266.37 308.96,266.37 A05.D1 | A23.T2 75.28,228.27 80.36,228.27 A23.T1 | A26.U2 40.36,225.09 42.58,225.09 42.58,222.87 A26.V1 43.53,221.92 45.44,220.02 78.46,220.02 80.36,221.92 A23.V1 81.63,222.55 83.86,224.78 A23.U1 | B22.T2 87.98,158.42 93.06,158.42 B22.T1 | B22.V1 94.33,152.71 96.56,154.93 B22.U1 | B23.C2 78.46,199.7 79.73,198.43 88.62,198.43 89.89,199.7 B22.C2 94.65,200.01 96.24,198.43 104.81,198.43 104.97,198.58 | 104.97,198.58 105.13,198.43 110.21,198.43 111.48,199.7 115.29,199.7 B20.C2 116.24,199.38 120.69,199.38 120.69,196.84 122.27,195.25 126.72,195.25 127.99,193.98 AB19.BE2 129.26,193.98 132.12,193.98 136.56,198.43 139.42,198.43 140.69,199.7 B18.C2 141.96,199.7 143.23,198.43 161.96,198.43 163.23,199.7 166.09,199.7 B16.C2 167.36,199.7 167.68,199.38 171.49,199.38 172.44,198.43 174.66,198.43 175.93,199.7 178.79,199.7 B15.C2 180.06,199.7 180.69,199.06 184.5,199.06 185.14,198.43 187.36,198.43 188.63,199.7 191.49,199.7 B14.C2 192.76,199.7 194.03,198.43 199.11,198.43 200.7,200.01 B13.C2 205.46,199.7 206.09,199.06 209.9,199.06 210.54,198.43 212.76,198.43 213.4,199.06 215.3,199.06 215.94,199.7 216.89,199.7 B12.C2 218.16,199.7 218.48,199.38 222.29,199.38 223.24,198.43 225.46,198.43 226.73,199.7 229.59,199.7 B11.C2 230.86,199.7 231.18,199.38 234.99,199.38 235.94,198.43 237.21,198.43 238.48,199.7 242.29,199.7 B10.C2 243.56,199.7 244.83,198.43 253.72,198.43 254.99,199.7 B09.C2 256.26,199.7 257.53,198.43 262.61,198.43 263.24,199.06 267.05,199.06 267.69,199.7 B08.C2 268.96,199.7 269.59,199.06 273.4,199.06 274.04,198.43 276.26,198.43 277.53,199.7 280.39,199.7 B07.C2 281.66,199.7 282.93,198.43 288.01,198.43 289.6,200.01 B06.C2 294.36,199.7 295.63,198.43 300.71,198.43 301.98,199.7 305.79,199.7 B05.C2 307.06,199.7 312.14,199.7 B05.C1 313.41,199.7 318.49,199.7 B04.C2 319.76,199.7 323.25,199.7 324.52,198.43 326.11,198.43 326.74,199.06 330.55,199.06 331.19,199.7 B03.C2 332.46,199.7 333.73,198.43 341.67,198.43 342.94,199.7 343.89,199.7 B02.C2 345.16,199.7 347.06,199.7 349.29,197.47 353.1,197.47 353.41,197.15 AB01.BD2
  Bottom 0.635: 104.97,198.58 103.86,199.7 B21.C2 | A16.T1 170.53,228.27 170.85,227.95 174.66,227.95 175.61,227 180.69,227 181.96,228.27 A15.T1 186.73,228.59 188.31,227 189.58,227 190.22,227.64 194.03,227.64 194.66,228.27 A14.T1 | v84.17,242.56 84.17,242.87
I/O_0_TO_AC\  (via drill 0.61)
  Top 0.254: v309.6,175.56 B05.L1 | A04.P2 318.81,237.48 318.81,233.67 317.54,232.4 317.54,221.92 316.58,220.97 316.58,206.05 317.22,205.41 317.22,177.15 v315.63,175.56 315.95,175.25 315.95,174.93 317.54,173.34 317.54,88.57 316.58,87.62 316.58,72.38 317.22,71.74 317.22,69.2 316.9,68.88 316.9,66.03 317.54,65.39 317.54,56.82 317.22,56.5 317.22,53.01 317.54,52.69 317.54,36.82 318.81,35.55 D04.P2
  Bottom 0.254: v309.6,175.56 309.92,175.88 315.31,175.88 v315.63,175.56
I/O_1_TO_CA_INH\  (via drill 0.61)
  Top 0.254: v293.09,11.42 293.09,19.35 292.14,20.31 292.14,22.53 292.45,22.85 292.45,30.15 294.99,32.69 294.99,35.55 294.68,35.86 294.68,39.99 294.04,40.63 D06.M2 | v114.34,10.46 114.34,27.29 114.02,27.61 v114.02,147.31 | v134.97,147.31 134.66,147.62 134.66,153.98 133.7,154.93 133.7,172.39 133.07,173.02 v133.07,294.31 | v260.39,296.22 273.72,296.22 273.72,289.55 v274.67,288.6 | v291.5,287.96 291.82,287.64 291.82,270.5 292.14,270.18 292.14,268.59 294.99,265.74 294.99,261.29 294.68,260.97 294.68,258.11 295.31,257.48 295.31,249.23 294.68,248.59 294.68,245.73 294.04,245.1 A06.M2 | v286.74,201.6 286.1,202.24 286.1,209.54 285.47,210.17 285.47,218.11 v285.79,218.43 | v280.07,218.74 279.75,219.06 279.75,240.65 v280.71,241.61
  Route2 0.254: v281.34,195.57 281.34,195.89 286.74,201.28 v286.74,201.6
  Route15 0.254: v281.34,195.57 292.77,184.14 293.72,184.14 300.71,177.15 300.71,176.52 302.3,174.93 302.3,173.66 302.93,173.02 302.93,172.07 B05.N2
  Bottom 0.254: v293.09,11.42 292.77,11.1 272.77,11.1 272.45,10.78 258.16,10.78 256.26,8.88 234.03,8.88 232.13,10.78 221.65,10.78 221.02,10.15 114.65,10.15 v114.34,10.46 | v114.02,147.31 132.43,147.31 132.75,147.62 134.66,147.62 v134.97,147.31 | v133.07,294.31 133.39,293.99 145.13,293.99 145.45,293.68 173.39,293.68 174.03,294.31 203.55,294.31 203.87,293.99 205.78,293.99 208,296.22 230.86,296.22 231.81,295.26 234.03,295.26 234.99,296.22 v260.39,296.22 | v274.67,288.6 275.63,287.64 291.18,287.64 v291.5,287.96 | v285.79,218.43 285.47,218.74 v280.07,218.74 | v280.71,241.61 281.66,242.56 289.91,242.56 291.5,244.14 293.09,244.14 A06.M2
I/O_ADDR_ACC\  (via drill 0.61)
  Top 0.254: v307.69,55.23 307.69,46.98 307.38,46.66 307.38,42.85 307.69,42.53 307.69,40.63 307.38,40.31 307.38,37.45 307.69,37.14 307.69,34.28 307.38,33.96 307.38,29.83 306.74,29.2 D05.S2 | v305.15,57.77 305.15,61.27 306.74,62.85 306.74,65.08 308.01,66.35 308.01,68.57 307.06,69.52 v307.06,71.43 | v324.2,71.74 323.89,72.06 323.89,74.92 325.16,76.19 v325.16,76.5 | v345.48,78.09 345.16,78.41 345.16,91.74 C02.U2 | v307.06,227.95 306.74,228.27 306.74,231.13 A05.S2 | v330.24,203.51 330.24,177.79 329.92,177.47 329.92,173.34 329.6,173.02 329.6,172.39 330.24,171.76 330.24,142.55 329.6,141.91 329.6,140.64 329.92,140.32 329.92,96.83 330.55,96.19 330.55,91.11 331.82,89.84 v331.82,79.05
  Route15 0.254: v307.06,227.95 307.06,227.64 309.92,224.78 309.92,223.83 310.87,222.87 310.87,217.16 317.85,210.17 319.76,210.17 324.84,205.09 327.38,205.09 327.7,204.77 328.97,204.77 v330.24,203.51
  Bottom 0.254: v305.15,57.77 v307.69,55.23 | v307.06,71.43 317.85,71.43 318.17,71.11 322.93,71.11 323.57,71.74 v324.2,71.74 | v325.16,76.5 325.47,76.19 330.87,76.19 332.78,78.09 | 332.78,78.09 v345.48,78.09 | v331.82,79.05 332.78,78.09
I/O_B-BRK  (via drill 0.61)
  Top 0.254: v305.15,24.12 305.15,29.2 305.79,29.83 305.79,33.96 306.11,34.28 D05.P2 | v328.65,17.45 329.6,17.45 335.32,11.74 372.78,11.74 372.78,52.69 v372.46,53.01 | v334.36,244.14 334.05,243.83 334.05,242.24 333.41,241.61 333.41,240.33 v333.73,240.02
  Route2 0.254: v364.21,62.53 364.21,63.81 364.84,64.44 364.84,67.61 365.16,67.93 365.16,73.01 366.75,74.6 366.75,97.78 v363.26,101.27 | v360.72,105.08 360.72,106.35 361.67,107.3 361.67,110.16 362.3,110.8 362.3,121.27 356.91,126.67 356.91,127.94 358.49,129.53 358.49,131.11 360.08,132.7 C01.D1 | v309.6,238.43 310.87,238.43 v318.49,246.05
  Route15 0.254: v372.46,53.01 370.56,54.92 370.56,56.18 v364.21,62.53 | v333.73,240.02 333.73,235.57 333.09,234.94 337.54,230.49 338.49,230.49 339.44,229.54 339.44,227 340.08,226.36 340.08,221.6 340.71,220.97 341.98,220.97 343.89,219.06 343.89,217.48 345.79,215.57 347.7,215.57 350.87,212.39 350.87,208.27 352.14,207 352.14,201.6 357.86,195.89 357.86,194.93 358.49,194.3 358.49,193.03 359.13,192.39 359.13,189.22 364.53,183.82 364.53,181.92 364.84,181.6 364.84,164.14 365.16,163.82 365.16,151.12 366.75,149.53 366.75,142.55 359.13,134.93 360.08,133.97 C01.D1
  Bottom 0.254: v305.15,24.12 305.47,23.8 321.98,23.8 328.33,17.45 v328.65,17.45 | v363.26,101.27 364.53,101.27 365.16,101.91 365.16,103.49 362.3,103.49 v360.72,105.08 | v309.6,238.43 307.06,238.43 A05.P2 | v318.49,246.05 318.81,245.73 332.78,245.73 v334.36,244.14
I/O_B-RUN  (via drill 0.61)
  Top 0.254: v359.76,29.2 361.67,31.1 361.67,52.06 360.72,53.01 v360.72,54.28 | v337.86,79.36 338.17,79.68 338.17,88.89 v337.86,89.21 | v346.11,214.62 v346.11,216.52
  Route2 0.254: v337.86,89.21 337.86,89.84 352.14,104.13 352.14,107.94 360.72,116.51 v360.72,116.83
  Route15 0.254: v360.72,54.28 360.72,54.92 359.13,56.5 359.13,60.31 354.37,65.08 354.05,65.08 353.41,65.71 353.41,67.93 v342.3,79.05 | v363.57,120.32 363.57,121.91 367.38,125.72 367.38,130.48 v364.21,133.65 | v334.68,218.11 321.35,231.45 319.76,231.45 A04.S2 | v353.1,211.12 353.1,206.05 357.22,201.92 358.18,201.92 v364.84,195.25 | v363.57,183.5 361.03,180.96 v363.26,178.74 | v360.72,167.31 359.13,165.72 359.13,163.82 v360.72,162.23 | v351.51,158.1 351.51,156.83 359.45,148.89 359.45,147.31 363.26,143.5 C01.A1
  Bottom 0.254: v359.76,29.2 357.86,27.29 350.24,27.29 349.92,27.61 347.06,27.61 346.75,27.29 337.54,27.29 337.22,27.61 334.36,27.61 334.05,27.29 324.84,27.29 324.52,27.61 320.39,27.61 319.76,28.25 D04.S2 | v342.3,79.05 341.98,79.36 v337.86,79.36 | v360.72,116.83 363.57,119.69 v363.57,120.32 | v364.21,133.65 364.53,133.97 365.16,133.97 365.48,134.29 365.48,142.23 363.89,142.23 C01.A1 | v334.68,218.11 335.63,217.16 345.48,217.16 v346.11,216.52 | v346.11,214.62 346.43,214.3 349.92,214.3 v353.1,211.12 | v364.84,195.25 364.84,194.3 365.8,193.34 365.8,183.5 v363.57,183.5 | v363.26,178.74 363.26,176.83 361.67,175.25 361.67,167.31 v360.72,167.31 | v360.72,162.23 360.08,161.59 358.81,161.59 357.54,160.33 353.73,160.33 v351.51,158.1
I/O_BAC_00  (via drill 0.61)
  Top 0.254: v343.57,120.96 343.25,120.64 343.25,94.28 v343.89,93.65 | v341.67,91.43 342.62,90.47 342.62,80 343.25,79.36 343.25,74.92 v342.3,73.97 | v346.11,73.33 345.79,73.01 345.79,72.06 344.52,70.79 v344.52,70.47 | v314.36,273.36 311.19,270.18 311.19,258.75 v310.87,258.43 | v300.71,247.64 298.8,245.73 298.8,243.19 v299.12,242.87 | v292.77,221.29 291.82,220.33 291.82,210.49 v292.14,210.17
  Route2 0.254: v310.87,258.43 305.15,252.72 305.15,252.08 v300.71,247.64 | v290.23,232.71 294.68,228.27 292.14,225.73 292.14,221.92 v292.77,221.29
  Route15 0.254: v343.57,120.96 342.62,121.91 342.62,127.62 341.98,128.26 341.98,128.89 339.44,131.43 339.44,137.15 338.17,138.42 340.4,140.64 340.4,141.27 339.13,142.55 338.81,142.55 C03.A1 337.54,142.86 336.27,144.13 332.78,140.64 330.24,140.64 329.28,141.59 324.84,141.59 322.3,144.13 321.98,144.13 304.52,161.59 304.52,172.39 302.93,173.98 302.93,175.25 301.34,176.83 301.34,181.92 298.8,184.46 298.8,186.36 291.82,193.34 291.82,204.14 288.96,207 v292.14,210.17
  Bottom 0.254: v343.89,93.65 v341.67,91.43 | v342.3,73.97 342.62,74.28 345.16,74.28 v346.11,73.33 | v344.52,70.47 347.38,70.47 D02.B1 | v314.36,273.36 315.31,274.31 322.93,274.31 323.25,273.99 326.11,273.99 326.43,274.31 335.63,274.31 335.95,273.99 338.81,273.99 339.13,274.31 341.98,274.31 343.25,273.04 A02.B1 | v299.12,242.87 299.12,239.38 293.09,239.38 288.96,235.26 288.96,233.35 289.6,233.35 v290.23,232.71
I/O_BAC_01  (via drill 0.61)
  Top 0.254: v364.21,90.47 364.53,90.16 364.53,77.46 v364.21,77.14 | v344.84,258.75 345.79,257.8 345.79,247.64 v345.16,247 | v350.24,246.68 349.6,246.05 349.6,243.51 350.24,242.87 v350.24,240.65 | v357.54,229.54 358.18,228.9 358.18,226.36 358.49,226.05 358.49,223.51 v358.18,223.19 | v363.26,173.02 363.89,172.39 v363.89,169.85
  Route2 0.254: 343.89,132.7 347.06,129.53 347.06,129.21 348.02,128.26 348.33,128.26 349.29,127.3 349.29,126.99 350.24,126.03 v351.51,127.3 | 343.89,132.7 338.81,137.78 337.54,137.78 335.32,135.56 335.32,133.97 C03.D1 | v348.33,262.88 346.11,260.66 346.11,260.02 v344.84,258.75 | v350.24,240.65 359.45,231.45 v357.54,229.54 | v358.18,223.19 359.13,222.24 359.13,221.6 366.11,214.62 v359.13,207.63 | v363.26,188.9 362.3,187.95 362.3,173.98 v363.26,173.02 | v363.89,169.85 368.97,164.77 368.97,158.42 361.99,151.43 361.99,150.48 344.21,132.7 343.89,132.7
  Route15 0.254: v355.95,126.99 358.49,124.45 358.49,119.05 359.13,118.41 359.13,117.14 360.72,115.56 361.03,115.56 361.67,114.92 361.67,108.57 364.84,105.4 364.84,102.86 365.16,102.54 365.16,91.43 v364.21,90.47 | v359.13,207.63 360.08,206.68 360.08,205.41 361.99,203.51 361.99,199.38 365.8,195.57 365.8,193.34 v364.84,192.39
  Bottom 0.254: v351.51,127.3 352.46,128.26 354.68,128.26 v355.95,126.99 | v364.21,77.14 368.34,77.14 368.97,76.5 368.97,69.2 362.62,69.2 358.18,64.76 352.46,64.76 351.51,63.81 348.33,63.81 D02.D1 | v348.33,262.88 348.02,262.88 348.02,266.05 A02.D1 | v345.16,247 345.48,246.68 346.75,246.68 347.06,246.37 349.92,246.37 v350.24,246.68 | v364.84,192.39 363.26,190.8 v363.26,188.9
I/O_BAC_02  (via drill 0.61)
  Top 0.254: v335.63,129.21 335.63,127.94 335.32,127.62 C03.F1 | D02.E1 350.87,64.76 352.46,66.35 352.46,73.33 351.51,74.28 351.51,83.81 352.14,84.44 352.14,102.54 352.46,102.86 352.46,131.11 v352.14,131.43 352.14,140.96 352.78,141.59 352.78,162.86 352.46,163.18 352.46,174.93 351.83,175.56 351.83,178.42 352.14,178.74 352.14,194.3 351.83,194.61 351.83,195.89 352.14,196.2 352.14,207 351.51,207.63 351.51,216.52 352.14,217.16 352.14,231.13 352.46,231.45 352.46,257.48 351.83,258.11 351.83,262.24 351.19,262.88 A02.E1
  Bottom 0.254: v335.63,129.21 335.63,131.43 v352.14,131.43
I/O_BAC_03  (via drill 0.61)
  Top 0.254: v372.46,55.55 372.78,55.87 v372.78,59.36
  Route15 0.254: v341.03,117.78 v338.17,120.64 | v368.02,250.81 368.02,247 364.21,243.19 365.16,242.24 365.16,239.38 365.48,239.06 365.48,236.21 366.43,235.26 366.43,220.02 371.51,214.93 371.51,213.35 372.15,212.71 372.15,212.08 372.78,211.44 372.78,150.17 368.65,146.04 368.65,126.67 369.61,125.72 369.61,118.41 v364.84,113.65
  Bottom 0.254: v372.46,55.55 367.7,55.55 367.38,55.23 352.46,55.23 351.51,54.28 D02.H1 | v372.78,59.36 372.78,95.55 373.42,96.19 373.42,113.97 364.84,113.97 | 364.84,113.97 364.53,113.97 363.57,113.02 352.78,113.02 347.06,118.73 343.57,118.73 342.62,117.78 v341.03,117.78 | v338.17,120.64 C03.J1 | v368.02,250.81 366.43,252.4 363.26,252.4 361.99,251.13 361.35,251.13 356.27,256.21 352.14,256.21 351.51,256.85 A02.H1 | v364.84,113.65 364.84,113.97
I/O_BAC_04  (via drill 0.61)
  Top 0.254: D02.J1 347.38,51.42 347.38,54.6 346.11,55.87 346.11,57.46 346.43,57.77 346.43,70.47 347.7,71.74 347.7,83.81 346.11,85.39 346.11,115.24 v345.79,115.56 346.11,115.88 346.11,158.42 345.79,158.74 345.79,193.98 346.43,194.61 346.43,203.82 347.7,205.09 347.7,217.48 346.11,219.06 346.11,232.08 345.48,232.71 345.48,235.57 345.79,235.89 345.79,238.75 345.48,239.06 345.48,243.19 346.43,244.14 346.43,252.4 347.38,253.35 A02.J1
  Bottom 0.254: v345.79,115.56 336.59,115.56 335.63,114.61 C03.L1
I/O_BAC_05  (via drill 0.61)
  Top 0.254: v335.95,111.11 335.95,109.21 335.32,108.57 C03.N1 | v372.46,96.51 372.78,96.19 372.78,60.63 371.51,59.36 371.51,52.06 v371.83,51.74 | v346.11,273.99 346.11,269.55 345.79,269.23 345.79,260.34 348.97,257.16 348.97,253.35 348.02,252.4 348.02,248.27 A02.L1 | v260.39,275.58 260.7,275.26 260.7,270.5 257.53,267.32 257.53,258.11 258.16,257.48 v258.16,257.16 | v242.29,229.54 241.02,228.27 241.02,226.05 v240.07,225.09 | v242.61,222.55 242.92,222.24 242.92,217.79 243.24,217.48 243.24,208.9 v242.61,208.27 | v254.99,192.08 259.43,187.63 v259.43,186.36 | v292.77,152.07 292.45,151.75 292.45,143.5 292.14,143.18 292.14,142.55 293.41,141.27 v293.41,139.05
  Route2 0.254: v258.16,257.16 258.16,256.21 252.77,250.81 252.77,249.86 248,245.1 248,239.38 245.46,236.84 245.46,236.21 241.65,232.4 241.65,230.18 v242.29,229.54 | v240.07,225.09 v242.61,222.55 | v284.2,156.2 287.37,153.02 287.69,153.34 289.6,153.34 289.91,153.66 291.18,153.66 v292.77,152.07 | v328.97,105.08 v330.87,106.99
  Route15 0.254: v242.61,208.27 243.56,209.22 243.88,208.9 244.19,208.9 244.83,208.27 244.83,206.68 253.72,197.79 253.72,193.34 v254.99,192.08 | v259.43,186.36 259.43,185.41 260.07,184.77 260.07,173.34 261.66,171.76 261.66,170.49 263.88,168.26 263.88,167.95 265.47,166.36 265.78,166.36 269.59,162.55 269.59,158.1 v270.23,157.47 | v293.41,139.05 294.99,139.05 295.63,138.42 295.63,132.7 315.31,113.02 319.12,113.02 323.89,108.25 323.89,107.94 324.52,107.3 326.74,107.3 v328.97,105.08
  Bottom 0.254: v335.95,111.11 337.22,109.84 368.34,109.84 368.65,110.16 369.29,110.16 372.46,106.99 v372.46,96.51 | v371.83,51.74 365.8,45.71 351.83,45.71 350.87,44.75 348.33,44.75 D02.L1 | v346.11,273.99 345.16,274.94 338.81,274.94 338.49,274.62 336.27,274.62 335.95,274.94 326.11,274.94 325.79,274.62 323.57,274.62 323.25,274.94 313.41,274.94 313.09,274.62 311.19,274.62 309.28,276.53 308.65,276.53 306.74,274.62 267.05,274.62 266.74,274.94 261.02,274.94 v260.39,275.58 | v270.23,157.47 273.4,154.29 281.98,154.29 283.88,156.2 v284.2,156.2 | v330.87,106.99 331.19,107.3 334.68,107.3 C03.N1
I/O_BAC_06  (via drill 0.61)
  Top 0.254: v354.37,76.5 354.37,72.69 355.32,71.74 355.32,48.57 352.78,46.03 352.78,43.49 351.19,41.9 D02.M1 | v339.13,76.5 338.81,76.82 338.81,90.79 339.44,91.43 339.44,99.36 337.86,100.95 v337.86,101.27 | v351.51,240.65 351.51,243.51 351.19,243.83 A02.M1 | v337.86,222.55 338.17,222.24 338.17,216.52 v337.86,216.21 | v324.52,192.08 324.2,191.76 v324.2,183.82
  Route2 0.254: v351.51,240.65 350.24,241.92 344.52,236.21 v344.52,235.89 | v343.89,227.32 342.3,227.32 337.86,222.87 v337.86,222.55 | v328.33,214.93 328.33,214.3 327.06,213.03 327.06,212.39 325.16,210.49 325.16,209.22 319.76,203.82 319.76,201.28 v322.62,198.43 | v321.03,174.93 322.3,173.66 319.44,170.8 319.44,170.49 317.54,168.58 317.54,168.26 316.9,167.63 316.27,167.63 315.63,168.26 314.68,167.31 314.68,166.68 310.23,162.23 310.23,161.28 308.01,159.05 308.01,151.43 306.42,149.85 306.42,146.67 304.84,145.08 304.84,143.81 302.93,141.91 302.93,141.27 301.98,140.32 301.98,139.37 301.03,138.42 300.07,138.42 298.8,137.15 298.8,130.16 v297.22,128.58
  Route15 0.254: v344.52,233.99 344.52,233.67 345.79,232.4 345.79,229.22 v343.89,227.32 | v334.36,216.84 330.24,216.84 v328.33,214.93 | v322.62,198.43 323.57,197.47 323.57,194.3 324.2,193.66 324.2,192.39 v324.52,192.08 | v324.2,183.82 324.52,183.82 326.74,181.6 326.74,179.37 321.66,174.3 v321.03,174.93 | v297.22,128.58 301.34,124.45 301.34,123.49 302.3,122.54 303.25,122.54 319.44,106.35 326.43,106.35 v330.87,101.91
